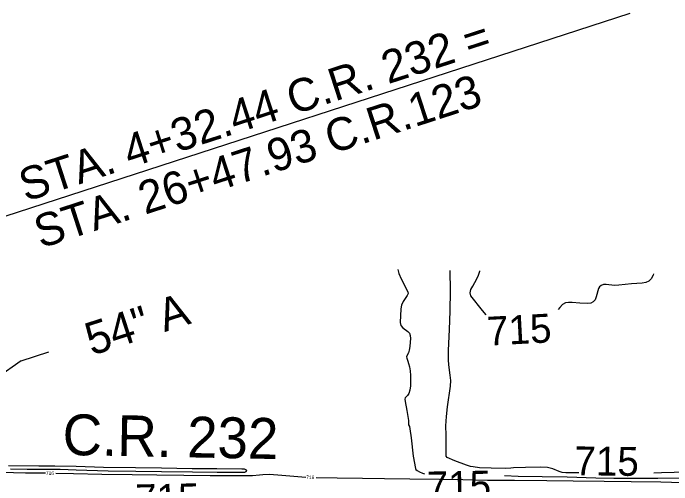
# Model space of a CAD drawing. Extents: x -468563856 to 36492962, y -306094093 to 11899197.
# Drawn here: x 1819296 to 1820050, y 531006 to 531546 of the extents above; entities that cross this region are included whole.
import ezdxf

# ---------------------------------------------------------------- set-up
doc = ezdxf.new("R2010")
doc.units = 0
for name, color, linetype in [('DT_X_Contour_Minor', 7, 'Continuous'), ('Level 19', 7, 'Continuous'), ('Level 40', 7, 'Continuous')]:
    doc.layers.add(name, color=color, linetype=linetype)

msp = doc.modelspace()

# ---------------------------------------------------------------- linework, layer by layer
at = {"layer": 'DT_X_Contour_Minor'}
for points in [[(1819736.63, 531252.6), (1819737.58, 531248.17), (1819740.11, 531241.82), (1819747.81, 531227.12), (1819748.1, 531225.09), (1819747.14, 531222.96), (1819742.75, 531215.78), (1819740.84, 531211.54), (1819739.96, 531207.5), (1819739.03, 531191.81), (1819739.86, 531188.4), (1819742.18, 531185.7), (1819748.08, 531181.54), (1819749.85, 531179.48), (1819750.67, 531176.96), (1819750.87, 531173.58), (1819750.72, 531169.17), (1819750.29, 531164.42), (1819749.58, 531160.23), (1819748.62, 531157.28), (1819746.89, 531153.88), (1819746.57, 531152.55), (1819746.66, 531151.12), (1819747.9, 531147.49), (1819748.81, 531144.86), (1819749.71, 531141.29), (1819750.43, 531136.6), (1819750.9, 531131.12), (1819751.07, 531125.27), (1819750.88, 531119.51), (1819750.27, 531114.39), (1819749.16, 531110.5), (1819747.59, 531108.19), (1819744.77, 531105.74), (1819744.41, 531104.06), (1819744.77, 531101.31), (1819746.68, 531091.16), (1819748.48, 531079.61), (1819748.7, 531075.35), (1819748.6, 531074.64), (1819749.73, 531072.7), (1819750.27, 531070.08), (1819751.66, 531059.87), (1819754.17, 531038.68), (1819756.54, 531024.83), (1819757.21, 531023.44), (1819758.63, 531022.45), (1819761.24, 531021.03), (1819764.81, 531019.39), (1819766.96, 531018.67)], [(1819943.68, 531019.82), (1819934.12, 531019.76), (1819928.7, 531019.82), (1819924.62, 531020.18), (1819921.25, 531021.09), (1819913.79, 531024.36), (1819907.83, 531025.7), (1819899.57, 531026.22), (1819882.48, 531025.89), (1819868.98, 531025.24), (1819865.68, 531024.98), (1819860.28, 531024.81), (1819843.18, 531024.99), (1819829.97, 531025.56), (1819822.51, 531026.44), (1819819.48, 531027.07), (1819814.92, 531028.45), (1819801.67, 531033.53), (1819792.95, 531037.43), (1819791.84, 531038.93), (1819791.79, 531045.84), (1819791.66, 531063.02), (1819791.54, 531073.46), (1819792.1, 531084.05), (1819793.34, 531095.2), (1819796.71, 531119.12), (1819796.95, 531125.33), (1819796.54, 531131.56), (1819795, 531143.54), (1819794.59, 531149.07), (1819794.56, 531159.84), (1819795.52, 531184.02), (1819796.31, 531205.03), (1819796.8, 531228.04), (1819796.23, 531251.61)], [(1819837.68, 531200.47), (1819833.55, 531205.52), (1819820.21, 531222.3), (1819819.34, 531225.72), (1819820.17, 531229.53), (1819822.15, 531233.62), (1819826.85, 531241.95), (1819828.79, 531246.2), (1819830.38, 531250.75), (1819830.44, 531251.01)], [(1820029.14, 531247.5), (1820028.66, 531245.95), (1820026.58, 531241.96), (1820023.8, 531239.11), (1820020.3, 531237.58), (1820016.31, 531236.96), (1820003.77, 531236.06), (1819989.46, 531234.56), (1819984.94, 531234.43), (1819977.91, 531235.17), (1819974.93, 531235.44), (1819972.01, 531235.23), (1819969.35, 531234.41), (1819967.29, 531232.91), (1819966.02, 531230.68), (1819963.66, 531221.13), (1819962.24, 531217.91), (1819960.14, 531215.45), (1819957.22, 531214.12), (1819953.59, 531213.69), (1819944.86, 531214.08), (1819935.85, 531214.73), (1819931.93, 531214.81), (1819928.38, 531214.22), (1819925.01, 531212.47), (1819921.75, 531209.24), (1819920.16, 531206.88)], [(1819895.36, 531184.86), (1819890.58, 531184.6)], [(1819282.61, 531020.48), (1819310.2, 531019.87), (1819332.96, 531019.51)], [(1819293.11, 531024.2), (1819312.02, 531024.06), (1819349.84, 531023.71), (1819368.21, 531023.18), (1819404.87, 531022.14), (1819436.39, 531021.66), (1819465.98, 531021.22), (1819501.5, 531020.69), (1819529.52, 531020.41), (1819561.39, 531020.33), (1819562.68, 531021.26), (1819563.41, 531022.31), (1819563.2, 531022.72), (1819560.88, 531024.01), (1819557.82, 531023.97), (1819529.42, 531024.16), (1819501.15, 531024.37), (1819466.07, 531024.89), (1819436.26, 531025.31), (1819399.47, 531025.87), (1819368.32, 531026.78), (1819343.89, 531027.37), (1819325.48, 531027.5), (1819290.71, 531027.75)], [(1819858.47, 531016.5), (1819874.25, 531016.03), (1819901.63, 531015.56), (1819930.13, 531015), (1819963.03, 531014.01), (1819983.8, 531013.7), (1820018.21, 531013.65), (1820033.98, 531013.43), (1820062.78, 531014.12), (1820090.66, 531014.82), (1820095.79, 531015.2), (1820100.88, 531015.85), (1820104.86, 531016.84), (1820106.85, 531018.19), (1820106.8, 531019.62), (1820104.83, 531020.75), (1820101.19, 531021.33), (1820096.45, 531021.45), (1820081.35, 531020.88), (1820067.45, 531020.45), (1820038.31, 531019.53), (1820029.69, 531019.43)], [(1819344.96, 531019.27), (1819365.27, 531018.86), (1819397.59, 531018.29), (1819432.24, 531017.96), (1819460.59, 531017.58), (1819491.52, 531017.15), (1819521.44, 531016.71), (1819551.11, 531016.46), (1819570.02, 531016.6), (1819578.07, 531017.31), (1819581.8, 531017.88), (1819589.11, 531017.99), (1819599.02, 531017.43), (1819631.07, 531014.84)], [(1819643.06, 531014.48), (1819666.9, 531014.02), (1819695.98, 531013.52), (1819721.13, 531013.2), (1819750.34, 531012.81), (1819784.04, 531012.39), (1819810.69, 531011.89), (1819838.93, 531011.3), (1819869.9, 531011.21), (1819907.1, 531010.74), (1819937.02, 531010.46), (1819972.82, 531010.14), (1820003.71, 531009.72), (1820037.35, 531009.26), (1820074.26, 531008.3), (1820093.49, 531008.12), (1820127.08, 531008.25), (1820155.77, 531008.64), (1820184.94, 531008.41), (1820208.61, 531007.92), (1820244.29, 531007.51), (1820269.27, 531007.68), (1820300.38, 531007.87)]]:
    msp.add_lwpolyline(points, dxfattribs=at)
at = {"layer": 'Level 40'}
for q in [(1819336.94, 531158.26), (1819128.03, 531024.1)]:
    msp.add_line((1819305.32, 531147.99), q, dxfattribs=at)
msp.add_lwpolyline([(1819175.03, 531075.3), (1819271.41, 531308.82), (1820002.43, 531546.16)], dxfattribs=at)

# ---------------------------------------------------------------- texts
at = {"layer": 'Level 19'}
for s, height, rotation, p in [('715', 33, 3.07105, (1819839.54, 531165.34)), ('715', 33, 359.33048, (1819938.54, 531017)), ('716', 4, 358.8492, (1819333.57, 531017.49)), ('715', 33, 0.93392, (1819769.85, 530988.09)), ('716', 4, 358.90649, (1819631.67, 531012.69)), ('715', 33, 1.09435, (1819436.07, 530973.37))]:
    msp.add_text(s, height=height, rotation=rotation, dxfattribs=at).set_placement(p)
at = {"layer": 'Level 40'}
for s, height, rotation, p in [('STA. 4+32.44 C.R. 232 =', 37.5, 17.9864, (1819310.35, 531330.03)), ('STA. 26+47.93 C.R.123', 37.5, 17.9864, (1819327.72, 531276.53)), ('54" A', 37.5, 17.9864, (1819386.02, 531153.68)), ('C.R. 232', 46.8, 358.88653, (1819352.33, 531040.23))]:
    msp.add_text(s, height=height, rotation=rotation, dxfattribs=at).set_placement(p)

doc.saveas('drawing.dxf')
